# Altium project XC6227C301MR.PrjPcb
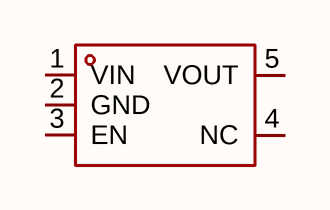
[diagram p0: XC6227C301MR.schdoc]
1 sheet, 1 parts. Net scope: global (net labels, ports and power ports of the same name join across sheets).

## Sheet XC6227C301MR.schdoc
size 127 x 101 mm

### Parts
U?  xc6227c301mr  [SOT-23-5_L2.9-W1.6-P0.95-LS2.8-BR]  (value not drawn)

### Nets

Not connected (* = marked no-connect by the designer): U? 1(VIN) 2(GND) 3(EN) 4(NC) 5(VOUT)

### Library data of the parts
U? = xc6227c301mr: 输出极性:正极;工作电压:6V;输出电压:3V;输出电流:700mA;电源纹波抑制比(PSRR):65dB@(1kHz);输出类型:固定;; Manufacturer: TECH PUBLIC(台舟); AddInBom: yes; ModelId: 7ba65df16e7b4570af156e925f9c37fe; ModelTransform: 114.173,114.173,0,90,0,0,0,0,0; Output Configuration: 正极; Voltage - Supply: 6V; Output Voltage: 3V; Output Current: 700mA; Voltage Dropout: 180mV@(100mA); standby current: 100uA; Output Type: 固定; Number of Outputs: 1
